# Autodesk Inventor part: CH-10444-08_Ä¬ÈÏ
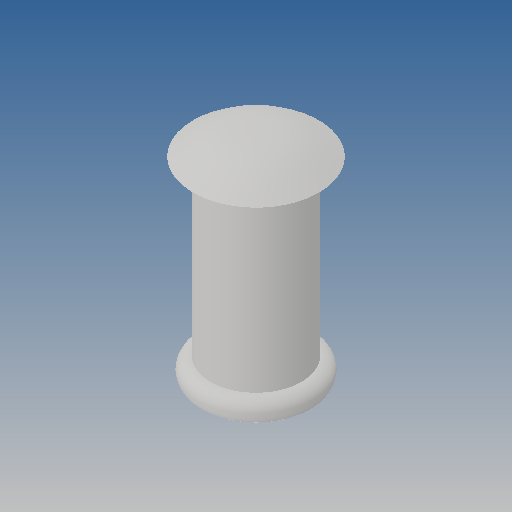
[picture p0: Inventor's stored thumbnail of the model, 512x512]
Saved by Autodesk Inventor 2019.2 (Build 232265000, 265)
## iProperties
Created: 2010-06
Part Number: CH-10444-08_Ä¬ÈÏ
Material: Ogólny
Document SubType Name: Modeling
Designer: CADENGINEERING4
Density: 1 g/cm^3
Appearance: Domyślna
Author: CADENGINEERING4
Revision Number: ÈÎºÎ
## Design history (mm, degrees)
feature "NONE"
node "Bryła1"
